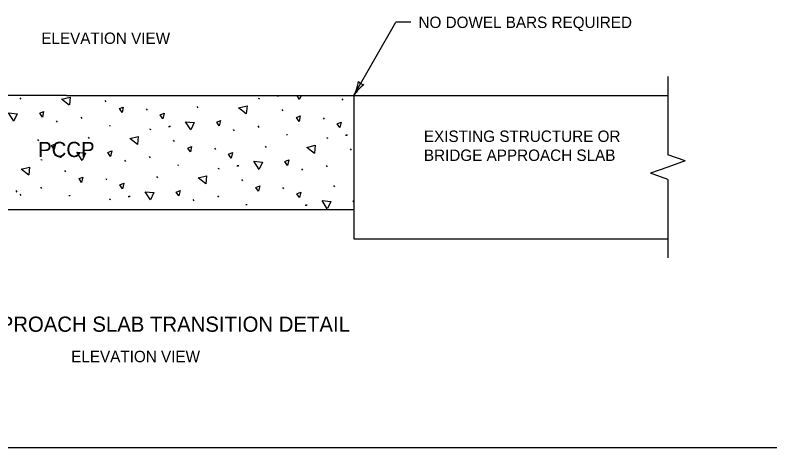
# Model space of a CAD drawing. Extents: x 49979.1 to 50021, y 49966.7 to 50011.4.
# Drawn here: x 50001.863 to 50005.834, y 49987.799 to 49990.077 of the extents above; entities that cross this region are included whole.
import ezdxf

# ---------------------------------------------------------------- set-up
doc = ezdxf.new("R2010")
doc.units = 0
for name, color, linetype in [('Level 1', 7, 'Continuous'), ('Level 13', 7, 'Continuous'), ('Level 15', 7, 'Continuous'), ('Level 2', 7, 'Continuous'), ('Level 3', 7, 'Continuous'), ('Level 6', 7, 'Continuous')]:
    doc.layers.add(name, color=color, linetype=linetype)

msp = doc.modelspace()

# ---------------------------------------------------------------- linework, layer by layer
at = {"layer": 'Level 1'}
for p, q in [((50002.1337, 49989.6538), (50000.6173, 49989.6538)), ((50002.1337, 49989.6538), (50003.6456, 49989.6538)), ((50003.6456, 49989.6538), (50005.2976, 49989.6538)), ((50003.6456, 49989.6538), (50003.6456, 49988.9)), ((50000.6173, 49989.0538), (50003.6456, 49989.0538)), ((50003.6456, 49988.9), (50005.2976, 49988.9))]:
    msp.add_line(p, q, dxfattribs=at)
msp.add_lwpolyline([(49999.3835, 49998.9992), (50016.7501, 49998.9992), (50016.7501, 49987.7988), (49999.3835, 49987.7988)], close=True, dxfattribs=at)
at = {"layer": 'Level 13'}
for p, q in [((50001.895, 49989.6346), (50001.8899, 49989.6416)), ((50003.142, 49989.6393), (50003.1494, 49989.6361)), ((50003.2422, 49989.6515), (50003.2486, 49989.6519)), ((50003.2457, 49989.6536), (50003.2492, 49989.6538)), ((50003.589, 49989.6286), (50003.5839, 49989.6357)), ((50002.3418, 49989.6196), (50002.3367, 49989.6267)), ((50002.8262, 49989.5881), (50002.8211, 49989.5952)), ((50002.5588, 49989.5764), (50002.5537, 49989.5834)), ((50003.273, 49989.5732), (50003.2678, 49989.5803)), ((50002.0859, 49989.5141), (50002.0808, 49989.5212)), ((50002.2156, 49989.5326), (50002.2104, 49989.5396)), ((50003.49, 49989.5299), (50003.4849, 49989.537)), ((50002.359, 49989.4949), (50002.3654, 49989.4953)), ((50002.5701, 49989.4784), (50002.5774, 49989.4751)), ((50002.6703, 49989.4905), (50002.6767, 49989.4909)), ((50002.6738, 49989.4926), (50002.6802, 49989.493)), ((50003.0171, 49989.4677), (50003.012, 49989.4747)), ((50003.1467, 49989.4861), (50003.1416, 49989.4932)), ((50002.2543, 49989.4271), (50002.2491, 49989.4342)), ((50003.2902, 49989.4484), (50003.2966, 49989.4488)), ((50003.5012, 49989.4319), (50003.5086, 49989.4287)), ((50003.6014, 49989.4441), (50003.6078, 49989.4445)), ((50003.605, 49989.4461), (50003.6113, 49989.4466)), ((50001.9869, 49989.4154), (50001.9818, 49989.4225)), ((50002.7011, 49989.4122), (50002.6959, 49989.4193)), ((50002.9181, 49989.369), (50002.9129, 49989.376)), ((50003.1855, 49989.3807), (50003.1803, 49989.3878)), ((50003.6322, 49989.3658), (50003.6271, 49989.3729)), ((50001.9981, 49989.3174), (50002.0055, 49989.3142)), ((50002.0983, 49989.3295), (50002.1047, 49989.3299)), ((50002.1019, 49989.3316), (50002.1083, 49989.332)), ((50002.4452, 49989.3067), (50002.44, 49989.3138)), ((50002.5748, 49989.3252), (50002.5696, 49989.3322)), ((50002.7182, 49989.2875), (50002.7246, 49989.2879)), ((50003.0295, 49989.2831), (50003.0359, 49989.2835)), ((50003.033, 49989.2852), (50003.0394, 49989.2856)), ((50003.506, 49989.2787), (50003.5008, 49989.2858)), ((50002.1291, 49989.2512), (50002.124, 49989.2583)), ((50002.9293, 49989.271), (50002.9367, 49989.2677)), ((50003.3763, 49989.2603), (50003.3712, 49989.2673)), ((50002.3462, 49989.208), (50002.341, 49989.2151)), ((50002.6135, 49989.2197), (50002.6084, 49989.2268)), ((50003.0603, 49989.2048), (50003.0552, 49989.2119)), ((50002.0029, 49989.1642), (50001.9977, 49989.1713)), ((50003.2773, 49989.1616), (50003.2722, 49989.1686)), ((50003.5447, 49989.1733), (50003.5395, 49989.1804)), ((50001.8733, 49989.1457), (50001.8681, 49989.1528)), ((50001.895, 49989.1269), (50001.8899, 49989.134)), ((50002.1463, 49989.1265), (50002.1527, 49989.1269)), ((50002.4576, 49989.1221), (50002.464, 49989.1225)), ((50002.4611, 49989.1242), (50002.4675, 49989.1246)), ((50002.934, 49989.1178), (50002.9289, 49989.1248)), ((50002.3574, 49989.11), (50002.3647, 49989.1068)), ((50002.8044, 49989.0993), (50002.7993, 49989.1063)), ((50003.0775, 49989.08), (50003.0839, 49989.0805)), ((50003.3887, 49989.0757), (50003.3951, 49989.0761)), ((50003.3923, 49989.0778), (50003.3987, 49989.0782))]:
    msp.add_line(p, q, dxfattribs=at)
for points in [[(50002.1479, 49989.6031), (50002.1075, 49989.6345), (50002.1518, 49989.6456), (50002.1481, 49989.6039)], [(50003.359, 49989.6333), (50003.3461, 49989.6538)], [(50003.3687, 49989.6538), (50003.3594, 49989.6341)], [(50002.4256, 49989.5641), (50002.4117, 49989.5844), (50002.4321, 49989.5931), (50002.4256, 49989.5641)], [(50003.0791, 49989.5566), (50003.0386, 49989.5881), (50003.083, 49989.5992), (50003.0792, 49989.5575)], [(50001.8559, 49989.5187), (50001.8286, 49989.5622), (50001.8741, 49989.5574), (50001.8563, 49989.5195)], [(50002.006, 49989.5399), (50001.9921, 49989.5603), (50002.0125, 49989.569), (50002.006, 49989.5399)], [(50002.6405, 49989.5313), (50002.6266, 49989.5516), (50002.647, 49989.5603), (50002.6405, 49989.5313)], [(50002.787, 49989.4723), (50002.7598, 49989.5157), (50002.8053, 49989.511), (50002.7875, 49989.4731)], [(50002.9372, 49989.4935), (50002.9233, 49989.5138), (50002.9437, 49989.5226), (50002.9372, 49989.4935)], [(50003.3568, 49989.5176), (50003.3429, 49989.538), (50003.3633, 49989.5467), (50003.3568, 49989.5176)], [(50003.5717, 49989.4849), (50003.5578, 49989.5052), (50003.5782, 49989.5139), (50003.5717, 49989.4849)], [(50002.5072, 49989.3956), (50002.4667, 49989.4271), (50002.5111, 49989.4382), (50002.5073, 49989.3965)], [(50002.0686, 49989.3703), (50002.0547, 49989.3906), (50002.0751, 49989.3994), (50002.0686, 49989.3703)], [(50003.4383, 49989.3492), (50003.3979, 49989.3807), (50003.4422, 49989.3918), (50003.4385, 49989.3501)], [(50002.2151, 49989.3113), (50002.1879, 49989.3547), (50002.2333, 49989.35), (50002.2155, 49989.3121)], [(50002.3652, 49989.3325), (50002.3513, 49989.3529), (50002.3718, 49989.3616), (50002.3652, 49989.3325)], [(50002.7849, 49989.3567), (50002.771, 49989.377), (50002.7914, 49989.3857), (50002.7849, 49989.3567)], [(50002.9997, 49989.3239), (50002.9858, 49989.3442), (50003.0062, 49989.3529), (50002.9997, 49989.3239)], [(50003.2964, 49989.2861), (50003.2825, 49989.3064), (50003.3029, 49989.3151), (50003.2964, 49989.2861)], [(50001.9352, 49989.2347), (50001.8948, 49989.2661), (50001.9391, 49989.2773), (50001.9354, 49989.2355)], [(50003.1463, 49989.2649), (50003.119, 49989.3083), (50003.1645, 49989.3036), (50003.1467, 49989.2657)], [(50002.2129, 49989.1957), (50002.199, 49989.216), (50002.2195, 49989.2247), (50002.2129, 49989.1957)], [(50002.8664, 49989.1882), (50002.826, 49989.2197), (50002.8703, 49989.2308), (50002.8666, 49989.1891)], [(50002.4278, 49989.1629), (50002.4139, 49989.1832), (50002.4343, 49989.192), (50002.4278, 49989.1629)], [(50002.7245, 49989.1251), (50002.7106, 49989.1455), (50002.731, 49989.1542), (50002.7245, 49989.1251)], [(50003.1441, 49989.1493), (50003.1302, 49989.1696), (50003.1506, 49989.1783), (50003.1441, 49989.1493)], [(50002.5743, 49989.1039), (50002.5471, 49989.1473), (50002.5926, 49989.1426), (50002.5748, 49989.1047)], [(50003.359, 49989.1165), (50003.3451, 49989.1368), (50003.3655, 49989.1455), (50003.359, 49989.1165)], [(50003.5055, 49989.0575), (50003.4783, 49989.1009), (50003.5238, 49989.0962), (50003.506, 49989.0583)], [(50003.6456, 49989.0934), (50003.6417, 49989.099), (50003.6456, 49989.1007)]]:
    msp.add_lwpolyline(points, dxfattribs=at)
at = {"layer": 'Level 15'}
msp.add_line((50003.7212, 49989.6538), (50003.979, 49989.6538), dxfattribs=at)
at = {"layer": 'Level 3'}
for p in [(50003.6456, 49989.6538), (50003.9451, 49990.0389)]:
    msp.add_line(p, (50003.8651, 49990.0389), dxfattribs=at)
for centre, radius, start, end in [((50003.4377, 49989.759), 0.233, 333.1433, 352.3932), ((50003.834, 49989.5358), 0.2223, 127.772, 147.9555), ((50003.7091, 49989.7652), 0.0548, 222.4548, 258.1772)]:
    msp.add_arc(centre, radius, start, end, dxfattribs=at)
at = {"layer": 'Level 6'}
for p, q in [((50005.2974, 49989.7538), (50005.2975, 49989.3417)), ((50005.3889, 49989.3093), (50005.2975, 49989.3417)), ((50005.2975, 49989.2769), (50005.2061, 49989.2445)), ((50005.3889, 49989.3093), (50005.2975, 49989.2769)), ((50005.2975, 49989.2121), (50005.2061, 49989.2445)), ((50005.2975, 49989.2121), (50005.2977, 49988.8))]:
    msp.add_line(p, q, dxfattribs=at)

# ---------------------------------------------------------------- texts
at = {"layer": 'Level 2'}
msp.add_text('NO DOWEL BARS REQUIRED', height=0.06, rotation=360, dxfattribs=at).set_placement((50003.9851, 49990.0089))
for s, height, p in [('ELEVATION VIEW', 0.06, (50002.0006, 49989.9251)), ('EXISTING STRUCTURE OR ', 0.06, (50004.0136, 49989.4092)), ('PCCP', 0.08, (50001.9837, 49989.3296)), ('BRIDGE APPROACH SLAB', 0.06, (50004.0136, 49989.3092)), ('EXISTING APPROACH SLAB TRANSITION DETAIL', 0.08, (50001.11, 49988.41)), ('ELEVATION VIEW', 0.06, (50002.1579, 49988.25))]:
    msp.add_text(s, height=height, dxfattribs=at).set_placement(p)

doc.saveas('drawing.dxf')
